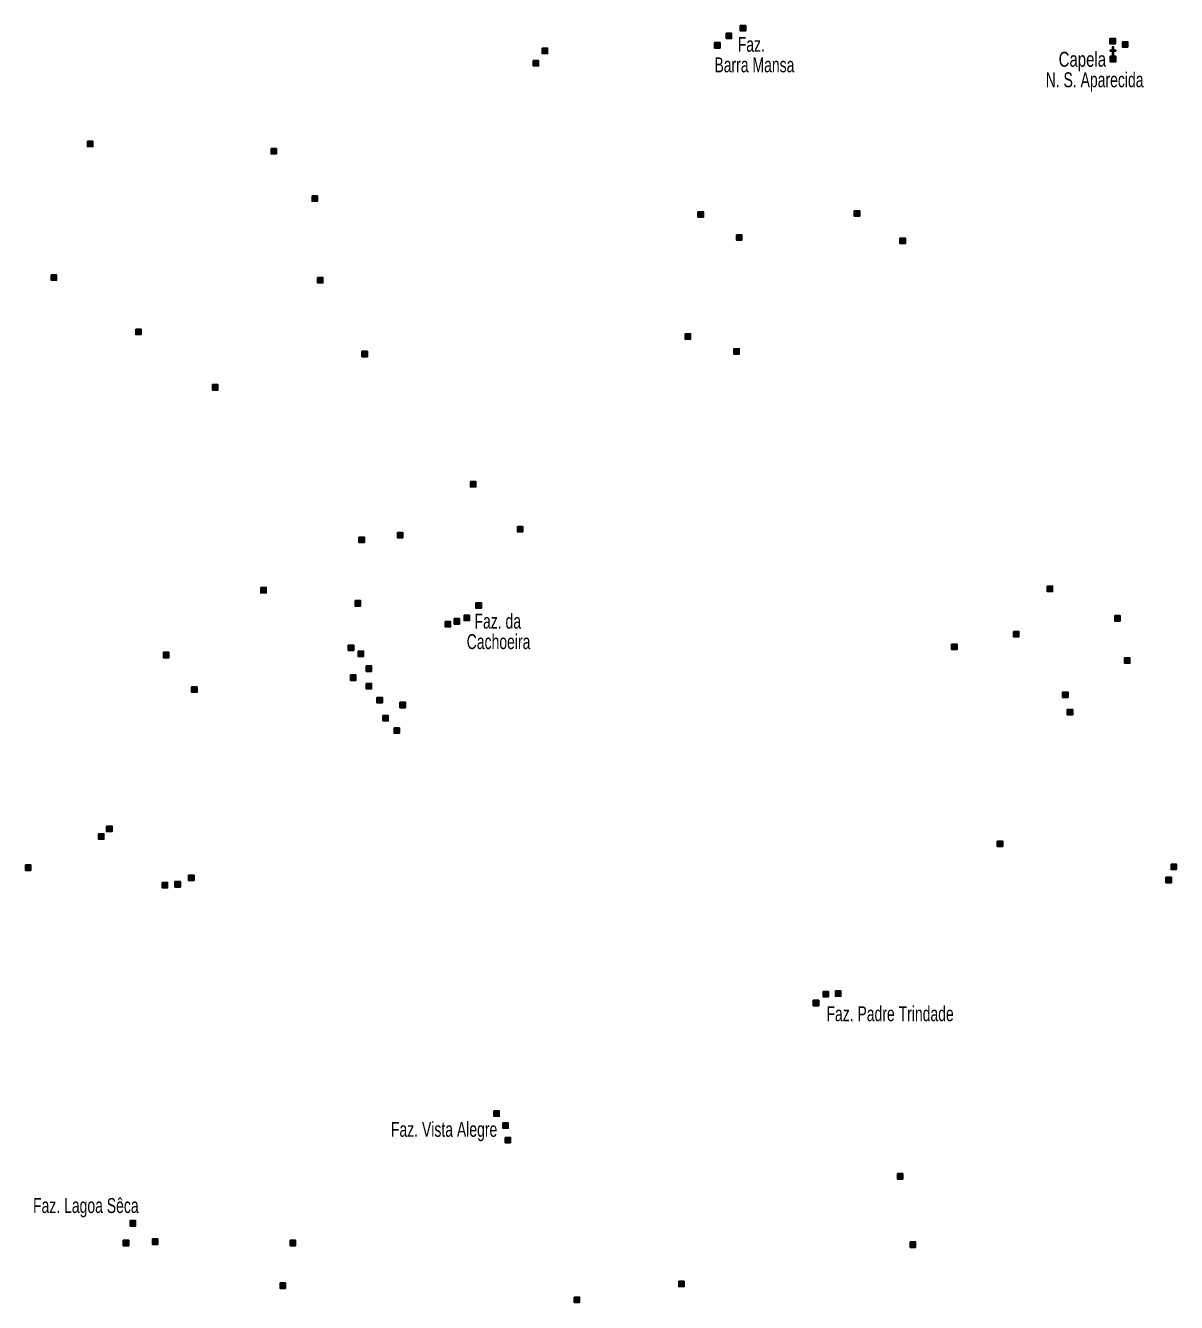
# Model space of a CAD drawing. Extents: x 447.8 to 473.9, y 7733.1 to 7760.8.
# Drawn here: x 454.66 to 460.83, y 7740 to 7746.84 of the extents above; entities that cross this region are included whole.
import ezdxf
from ezdxf.enums import TextEntityAlignment as Align

# ---------------------------------------------------------------- set-up
doc = ezdxf.new("R2010")
doc.units = 0
doc.header["$LTSCALE"] = 0.032
doc.layers.add('2', color=7, linetype='Continuous', lineweight=25)
doc.layers.add('6', color=7, linetype='Continuous', lineweight=25)
doc.layers.add('61', color=7, linetype='Continuous')

msp = doc.modelspace()

# ---------------------------------------------------------------- hatches: boundary and pattern name
at = {"layer": '2'}
for points in [[(458.4164, 7746.8001), (458.4454, 7746.8001), (458.4454, 7746.7711), (458.4164, 7746.7711)], [(458.4919, 7746.8413), (458.5209, 7746.8413), (458.5209, 7746.8123), (458.4919, 7746.8123)], [(457.4299, 7746.72), (457.4589, 7746.72), (457.4589, 7746.691), (457.4299, 7746.691)], [(458.3546, 7746.7498), (458.3836, 7746.7498), (458.3836, 7746.7208), (458.3546, 7746.7208)], [(460.474, 7746.7727), (460.503, 7746.7727), (460.503, 7746.7437), (460.474, 7746.7437)], [(460.5404, 7746.7544), (460.5694, 7746.7544), (460.5694, 7746.7254), (460.5404, 7746.7254)], [(457.3818, 7746.6537), (457.4108, 7746.6537), (457.4108, 7746.6247), (457.3818, 7746.6247)], [(454.9922, 7746.2211), (455.0212, 7746.2211), (455.0212, 7746.1921), (454.9922, 7746.1921)], [(455.9764, 7746.1821), (456.0054, 7746.1821), (456.0054, 7746.1531), (455.9764, 7746.1531)], [(456.1962, 7745.9281), (456.2252, 7745.9281), (456.2252, 7745.8991), (456.1962, 7745.8991)], [(458.2653, 7745.8434), (458.2943, 7745.8434), (458.2943, 7745.8144), (458.2653, 7745.8144)], [(459.103, 7745.848), (459.132, 7745.848), (459.132, 7745.819), (459.103, 7745.819)], [(458.4713, 7745.7198), (458.5003, 7745.7198), (458.5003, 7745.6908), (458.4713, 7745.6908)], [(459.3479, 7745.7015), (459.3769, 7745.7015), (459.3769, 7745.6725), (459.3479, 7745.6725)], [(454.7977, 7745.5046), (454.8267, 7745.5046), (454.8267, 7745.4756), (454.7977, 7745.4756)], [(456.2259, 7745.4909), (456.2549, 7745.4909), (456.2549, 7745.4619), (456.2259, 7745.4619)], [(455.2509, 7745.214), (455.2799, 7745.214), (455.2799, 7745.185), (455.2509, 7745.185)], [(458.1966, 7745.1888), (458.2256, 7745.1888), (458.2256, 7745.1598), (458.1966, 7745.1598)], [(456.464, 7745.0949), (456.493, 7745.0949), (456.493, 7745.0659), (456.464, 7745.0659)], [(458.4576, 7745.1087), (458.4866, 7745.1087), (458.4866, 7745.0797), (458.4576, 7745.0797)], [(455.6629, 7744.9164), (455.6919, 7744.9164), (455.6919, 7744.8874), (455.6629, 7744.8874)], [(457.0453, 7744.3968), (457.0743, 7744.3968), (457.0743, 7744.3678), (457.0453, 7744.3678)], [(456.6539, 7744.1245), (456.6829, 7744.1245), (456.6829, 7744.0955), (456.6539, 7744.0955)], [(457.2971, 7744.1565), (457.3261, 7744.1565), (457.3261, 7744.1275), (457.2971, 7744.1275)], [(456.4479, 7744.0993), (456.4769, 7744.0993), (456.4769, 7744.0703), (456.4479, 7744.0703)], [(455.9215, 7743.8292), (455.9505, 7743.8292), (455.9505, 7743.8002), (455.9215, 7743.8002)], [(460.1376, 7743.8361), (460.1666, 7743.8361), (460.1666, 7743.8071), (460.1376, 7743.8071)], [(456.4273, 7743.7583), (456.4563, 7743.7583), (456.4563, 7743.7293), (456.4273, 7743.7293)], [(457.0751, 7743.7468), (457.1041, 7743.7468), (457.1041, 7743.7178), (457.0751, 7743.7178)], [(456.9103, 7743.6461), (456.9393, 7743.6461), (456.9393, 7743.6171), (456.9103, 7743.6171)], [(456.9584, 7743.6621), (456.9874, 7743.6621), (456.9874, 7743.6331), (456.9584, 7743.6331)], [(457.011, 7743.6804), (457.04, 7743.6804), (457.04, 7743.6514), (457.011, 7743.6514)], [(460.4992, 7743.6781), (460.5282, 7743.6781), (460.5282, 7743.6491), (460.4992, 7743.6491)], [(459.9568, 7743.5935), (459.9858, 7743.5935), (459.9858, 7743.5645), (459.9568, 7743.5645)], [(456.3907, 7743.5202), (456.4197, 7743.5202), (456.4197, 7743.4912), (456.3907, 7743.4912)], [(459.6249, 7743.5248), (459.6539, 7743.5248), (459.6539, 7743.4958), (459.6249, 7743.4958)], [(455.3996, 7743.4813), (455.4286, 7743.4813), (455.4286, 7743.4523), (455.3996, 7743.4523)], [(456.4434, 7743.4882), (456.4724, 7743.4882), (456.4724, 7743.4592), (456.4434, 7743.4592)], [(460.5519, 7743.4515), (460.5809, 7743.4515), (460.5809, 7743.4225), (460.5519, 7743.4225)], [(456.4022, 7743.36), (456.4312, 7743.36), (456.4312, 7743.331), (456.4022, 7743.331)], [(456.4868, 7743.4081), (456.5158, 7743.4081), (456.5158, 7743.3791), (456.4868, 7743.3791)], [(455.5507, 7743.2959), (455.5797, 7743.2959), (455.5797, 7743.2669), (455.5507, 7743.2669)], [(456.4868, 7743.3142), (456.5158, 7743.3142), (456.5158, 7743.2852), (456.4868, 7743.2852)], [(456.5441, 7743.2387), (456.5731, 7743.2387), (456.5731, 7743.2097), (456.5441, 7743.2097)], [(460.22, 7743.2684), (460.249, 7743.2684), (460.249, 7743.2394), (460.22, 7743.2394)], [(456.6677, 7743.2135), (456.6967, 7743.2135), (456.6967, 7743.1845), (456.6677, 7743.1845)], [(460.2451, 7743.1746), (460.2741, 7743.1746), (460.2741, 7743.1456), (460.2451, 7743.1456)], [(456.5761, 7743.1425), (456.6051, 7743.1425), (456.6051, 7743.1135), (456.5761, 7743.1135)], [(456.6356, 7743.0762), (456.6646, 7743.0762), (456.6646, 7743.0472), (456.6356, 7743.0472)], [(455.0952, 7742.5497), (455.1242, 7742.5497), (455.1242, 7742.5207), (455.0952, 7742.5207)], [(455.0517, 7742.5085), (455.0807, 7742.5085), (455.0807, 7742.4795), (455.0517, 7742.4795)], [(459.8698, 7742.4696), (459.8988, 7742.4696), (459.8988, 7742.4406), (459.8698, 7742.4406)], [(454.6603, 7742.3414), (454.6893, 7742.3414), (454.6893, 7742.3124), (454.6603, 7742.3124)], [(460.8013, 7742.346), (460.8303, 7742.346), (460.8303, 7742.317), (460.8013, 7742.317)], [(455.5347, 7742.2865), (455.5637, 7742.2865), (455.5637, 7742.2575), (455.5347, 7742.2575)], [(460.7739, 7742.2751), (460.8029, 7742.2751), (460.8029, 7742.2461), (460.7739, 7742.2461)], [(455.3928, 7742.2476), (455.4218, 7742.2476), (455.4218, 7742.2186), (455.3928, 7742.2186)], [(455.4614, 7742.2522), (455.4904, 7742.2522), (455.4904, 7742.2232), (455.4614, 7742.2232)], [(458.9359, 7741.6639), (458.9649, 7741.6639), (458.9649, 7741.6349), (458.9359, 7741.6349)], [(459.0023, 7741.6662), (459.0313, 7741.6662), (459.0313, 7741.6372), (459.0023, 7741.6372)], [(458.8833, 7741.6159), (458.9123, 7741.6159), (458.9123, 7741.5869), (458.8833, 7741.5869)], [(457.1712, 7741.0231), (457.2002, 7741.0231), (457.2002, 7740.9941), (457.1712, 7740.9941)], [(457.2193, 7740.959), (457.2483, 7740.959), (457.2483, 7740.93), (457.2193, 7740.93)], [(457.2307, 7740.8812), (457.2597, 7740.8812), (457.2597, 7740.8522), (457.2307, 7740.8522)], [(459.3342, 7740.6866), (459.3632, 7740.6866), (459.3632, 7740.6576), (459.3342, 7740.6576)], [(455.2211, 7740.4348), (455.2501, 7740.4348), (455.2501, 7740.4058), (455.2211, 7740.4058)], [(455.1845, 7740.3295), (455.2135, 7740.3295), (455.2135, 7740.3005), (455.1845, 7740.3005)], [(455.3401, 7740.3364), (455.3691, 7740.3364), (455.3691, 7740.3074), (455.3401, 7740.3074)], [(456.0794, 7740.3295), (456.1084, 7740.3295), (456.1084, 7740.3005), (456.0794, 7740.3005)], [(459.4029, 7740.3204), (459.4319, 7740.3204), (459.4319, 7740.2914), (459.4029, 7740.2914)], [(456.0245, 7740.1007), (456.0535, 7740.1007), (456.0535, 7740.0717), (456.0245, 7740.0717)], [(458.1623, 7740.1098), (458.1913, 7740.1098), (458.1913, 7740.0808), (458.1623, 7740.0808)], [(457.6015, 7740.0251), (457.6305, 7740.0251), (457.6305, 7739.9961), (457.6015, 7739.9961)]]:
    msp.add_hatch(color=256, dxfattribs=at).paths.add_polyline_path(points)
at = {"layer": '6'}
for points in [[(460.4927, 7746.6772), (460.4877, 7746.6772), (460.4877, 7746.7047), (460.4752, 7746.7047), (460.4752, 7746.7097), (460.4877, 7746.7097), (460.4877, 7746.7272), (460.4927, 7746.7272), (460.4927, 7746.7097), (460.5052, 7746.7097), (460.5052, 7746.7047), (460.4927, 7746.7047)], [(460.4752, 7746.6772), (460.4752, 7746.6472), (460.5052, 7746.6472), (460.5052, 7746.6772)]]:
    msp.add_hatch(color=256, dxfattribs=at).paths.add_polyline_path(points)

# ---------------------------------------------------------------- linework, layer by layer
at = {"layer": '2'}
for points in [[(458.4164, 7746.8001), (458.4454, 7746.8001), (458.4454, 7746.7711), (458.4164, 7746.7711)], [(458.4919, 7746.8413), (458.5209, 7746.8413), (458.5209, 7746.8123), (458.4919, 7746.8123)], [(457.4299, 7746.72), (457.4589, 7746.72), (457.4589, 7746.691), (457.4299, 7746.691)], [(458.3546, 7746.7498), (458.3836, 7746.7498), (458.3836, 7746.7208), (458.3546, 7746.7208)], [(460.474, 7746.7727), (460.503, 7746.7727), (460.503, 7746.7437), (460.474, 7746.7437)], [(460.5404, 7746.7544), (460.5694, 7746.7544), (460.5694, 7746.7254), (460.5404, 7746.7254)], [(457.3818, 7746.6537), (457.4108, 7746.6537), (457.4108, 7746.6247), (457.3818, 7746.6247)], [(454.9922, 7746.2211), (455.0212, 7746.2211), (455.0212, 7746.1921), (454.9922, 7746.1921)], [(455.9764, 7746.1821), (456.0054, 7746.1821), (456.0054, 7746.1531), (455.9764, 7746.1531)], [(456.1962, 7745.9281), (456.2252, 7745.9281), (456.2252, 7745.8991), (456.1962, 7745.8991)], [(458.2653, 7745.8434), (458.2943, 7745.8434), (458.2943, 7745.8144), (458.2653, 7745.8144)], [(459.103, 7745.848), (459.132, 7745.848), (459.132, 7745.819), (459.103, 7745.819)], [(458.4713, 7745.7198), (458.5003, 7745.7198), (458.5003, 7745.6908), (458.4713, 7745.6908)], [(459.3479, 7745.7015), (459.3769, 7745.7015), (459.3769, 7745.6725), (459.3479, 7745.6725)], [(454.7977, 7745.5046), (454.8267, 7745.5046), (454.8267, 7745.4756), (454.7977, 7745.4756)], [(456.2259, 7745.4909), (456.2549, 7745.4909), (456.2549, 7745.4619), (456.2259, 7745.4619)], [(455.2509, 7745.214), (455.2799, 7745.214), (455.2799, 7745.185), (455.2509, 7745.185)], [(458.1966, 7745.1888), (458.2256, 7745.1888), (458.2256, 7745.1598), (458.1966, 7745.1598)], [(456.464, 7745.0949), (456.493, 7745.0949), (456.493, 7745.0659), (456.464, 7745.0659)], [(458.4576, 7745.1087), (458.4866, 7745.1087), (458.4866, 7745.0797), (458.4576, 7745.0797)], [(455.6629, 7744.9164), (455.6919, 7744.9164), (455.6919, 7744.8874), (455.6629, 7744.8874)], [(457.0453, 7744.3968), (457.0743, 7744.3968), (457.0743, 7744.3678), (457.0453, 7744.3678)], [(456.6539, 7744.1245), (456.6829, 7744.1245), (456.6829, 7744.0955), (456.6539, 7744.0955)], [(457.2971, 7744.1565), (457.3261, 7744.1565), (457.3261, 7744.1275), (457.2971, 7744.1275)], [(456.4479, 7744.0993), (456.4769, 7744.0993), (456.4769, 7744.0703), (456.4479, 7744.0703)], [(455.9215, 7743.8292), (455.9505, 7743.8292), (455.9505, 7743.8002), (455.9215, 7743.8002)], [(460.1376, 7743.8361), (460.1666, 7743.8361), (460.1666, 7743.8071), (460.1376, 7743.8071)], [(456.4273, 7743.7583), (456.4563, 7743.7583), (456.4563, 7743.7293), (456.4273, 7743.7293)], [(457.0751, 7743.7468), (457.1041, 7743.7468), (457.1041, 7743.7178), (457.0751, 7743.7178)], [(456.9103, 7743.6461), (456.9393, 7743.6461), (456.9393, 7743.6171), (456.9103, 7743.6171)], [(456.9584, 7743.6621), (456.9874, 7743.6621), (456.9874, 7743.6331), (456.9584, 7743.6331)], [(457.011, 7743.6804), (457.04, 7743.6804), (457.04, 7743.6514), (457.011, 7743.6514)], [(460.4992, 7743.6781), (460.5282, 7743.6781), (460.5282, 7743.6491), (460.4992, 7743.6491)], [(459.9568, 7743.5935), (459.9858, 7743.5935), (459.9858, 7743.5645), (459.9568, 7743.5645)], [(456.3907, 7743.5202), (456.4197, 7743.5202), (456.4197, 7743.4912), (456.3907, 7743.4912)], [(459.6249, 7743.5248), (459.6539, 7743.5248), (459.6539, 7743.4958), (459.6249, 7743.4958)], [(455.3996, 7743.4813), (455.4286, 7743.4813), (455.4286, 7743.4523), (455.3996, 7743.4523)], [(456.4434, 7743.4882), (456.4724, 7743.4882), (456.4724, 7743.4592), (456.4434, 7743.4592)], [(460.5519, 7743.4515), (460.5809, 7743.4515), (460.5809, 7743.4225), (460.5519, 7743.4225)], [(456.4022, 7743.36), (456.4312, 7743.36), (456.4312, 7743.331), (456.4022, 7743.331)], [(456.4868, 7743.4081), (456.5158, 7743.4081), (456.5158, 7743.3791), (456.4868, 7743.3791)], [(455.5507, 7743.2959), (455.5797, 7743.2959), (455.5797, 7743.2669), (455.5507, 7743.2669)], [(456.4868, 7743.3142), (456.5158, 7743.3142), (456.5158, 7743.2852), (456.4868, 7743.2852)], [(456.5441, 7743.2387), (456.5731, 7743.2387), (456.5731, 7743.2097), (456.5441, 7743.2097)], [(460.22, 7743.2684), (460.249, 7743.2684), (460.249, 7743.2394), (460.22, 7743.2394)], [(456.6677, 7743.2135), (456.6967, 7743.2135), (456.6967, 7743.1845), (456.6677, 7743.1845)], [(460.2451, 7743.1746), (460.2741, 7743.1746), (460.2741, 7743.1456), (460.2451, 7743.1456)], [(456.5761, 7743.1425), (456.6051, 7743.1425), (456.6051, 7743.1135), (456.5761, 7743.1135)], [(456.6356, 7743.0762), (456.6646, 7743.0762), (456.6646, 7743.0472), (456.6356, 7743.0472)], [(455.0952, 7742.5497), (455.1242, 7742.5497), (455.1242, 7742.5207), (455.0952, 7742.5207)], [(455.0517, 7742.5085), (455.0807, 7742.5085), (455.0807, 7742.4795), (455.0517, 7742.4795)], [(459.8698, 7742.4696), (459.8988, 7742.4696), (459.8988, 7742.4406), (459.8698, 7742.4406)], [(454.6603, 7742.3414), (454.6893, 7742.3414), (454.6893, 7742.3124), (454.6603, 7742.3124)], [(460.8013, 7742.346), (460.8303, 7742.346), (460.8303, 7742.317), (460.8013, 7742.317)], [(455.5347, 7742.2865), (455.5637, 7742.2865), (455.5637, 7742.2575), (455.5347, 7742.2575)], [(460.7739, 7742.2751), (460.8029, 7742.2751), (460.8029, 7742.2461), (460.7739, 7742.2461)], [(455.3928, 7742.2476), (455.4218, 7742.2476), (455.4218, 7742.2186), (455.3928, 7742.2186)], [(455.4614, 7742.2522), (455.4904, 7742.2522), (455.4904, 7742.2232), (455.4614, 7742.2232)], [(458.9359, 7741.6639), (458.9649, 7741.6639), (458.9649, 7741.6349), (458.9359, 7741.6349)], [(459.0023, 7741.6662), (459.0313, 7741.6662), (459.0313, 7741.6372), (459.0023, 7741.6372)], [(458.8833, 7741.6159), (458.9123, 7741.6159), (458.9123, 7741.5869), (458.8833, 7741.5869)], [(457.1712, 7741.0231), (457.2002, 7741.0231), (457.2002, 7740.9941), (457.1712, 7740.9941)], [(457.2193, 7740.959), (457.2483, 7740.959), (457.2483, 7740.93), (457.2193, 7740.93)], [(457.2307, 7740.8812), (457.2597, 7740.8812), (457.2597, 7740.8522), (457.2307, 7740.8522)], [(459.3342, 7740.6866), (459.3632, 7740.6866), (459.3632, 7740.6576), (459.3342, 7740.6576)], [(455.2211, 7740.4348), (455.2501, 7740.4348), (455.2501, 7740.4058), (455.2211, 7740.4058)], [(455.1845, 7740.3295), (455.2135, 7740.3295), (455.2135, 7740.3005), (455.1845, 7740.3005)], [(455.3401, 7740.3364), (455.3691, 7740.3364), (455.3691, 7740.3074), (455.3401, 7740.3074)], [(456.0794, 7740.3295), (456.1084, 7740.3295), (456.1084, 7740.3005), (456.0794, 7740.3005)], [(459.4029, 7740.3204), (459.4319, 7740.3204), (459.4319, 7740.2914), (459.4029, 7740.2914)], [(456.0245, 7740.1007), (456.0535, 7740.1007), (456.0535, 7740.0717), (456.0245, 7740.0717)], [(458.1623, 7740.1098), (458.1913, 7740.1098), (458.1913, 7740.0808), (458.1623, 7740.0808)], [(457.6015, 7740.0251), (457.6305, 7740.0251), (457.6305, 7739.9961), (457.6015, 7739.9961)]]:
    msp.add_lwpolyline(points, close=True, dxfattribs=at)
at = {"layer": '6'}
for points in [[(460.4927, 7746.6772), (460.4877, 7746.6772), (460.4877, 7746.7047), (460.4752, 7746.7047), (460.4752, 7746.7097), (460.4877, 7746.7097), (460.4877, 7746.7272), (460.4927, 7746.7272), (460.4927, 7746.7097), (460.5052, 7746.7097), (460.5052, 7746.7047), (460.4927, 7746.7047)], [(460.4752, 7746.6772), (460.4752, 7746.6472), (460.5052, 7746.6472), (460.5052, 7746.6772)]]:
    msp.add_lwpolyline(points, close=True, dxfattribs=at)

# ---------------------------------------------------------------- texts
at = {"layer": '61', "width": 0.7}
for s, p in [('      Faz.', (458.3534, 7746.7005)), ('Barra Mansa', (458.3534, 7746.5905)), ('  Faz. da', (457.0254, 7743.6085)), ('Cachoeira', (457.0254, 7743.4985)), ('Faz. Padre Trindade', (458.9537, 7741.5039))]:
    msp.add_text(s, height=0.08, dxfattribs=at).set_placement(p)
at = {"layer": '61'}
for s, width, p in [('    Capela         ', 0.75, (460.6537, 7746.6204)), ('N. S. Aparecida', 0.7, (460.6537, 7746.5104)), ('Faz. Vista Alegre', 0.7, (457.1893, 7740.8841)), ('Faz. Lagoa Sêca', 0.7, (455.2666, 7740.4757))]:
    msp.add_text(s, height=0.08, dxfattribs=dict(at, width=width)).set_placement(p, align=Align.RIGHT)

doc.saveas('drawing.dxf')
